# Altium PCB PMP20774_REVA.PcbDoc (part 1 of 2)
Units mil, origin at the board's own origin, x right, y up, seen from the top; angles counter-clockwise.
Board outline 2225 x 750 mil, 4 copper layers (Top Layer, Signal Layer 1, Signal Layer 2, Bottom Layer), stack 61.2 mil thick; 80 components, 51 nets, 281 pads, 110 vias.
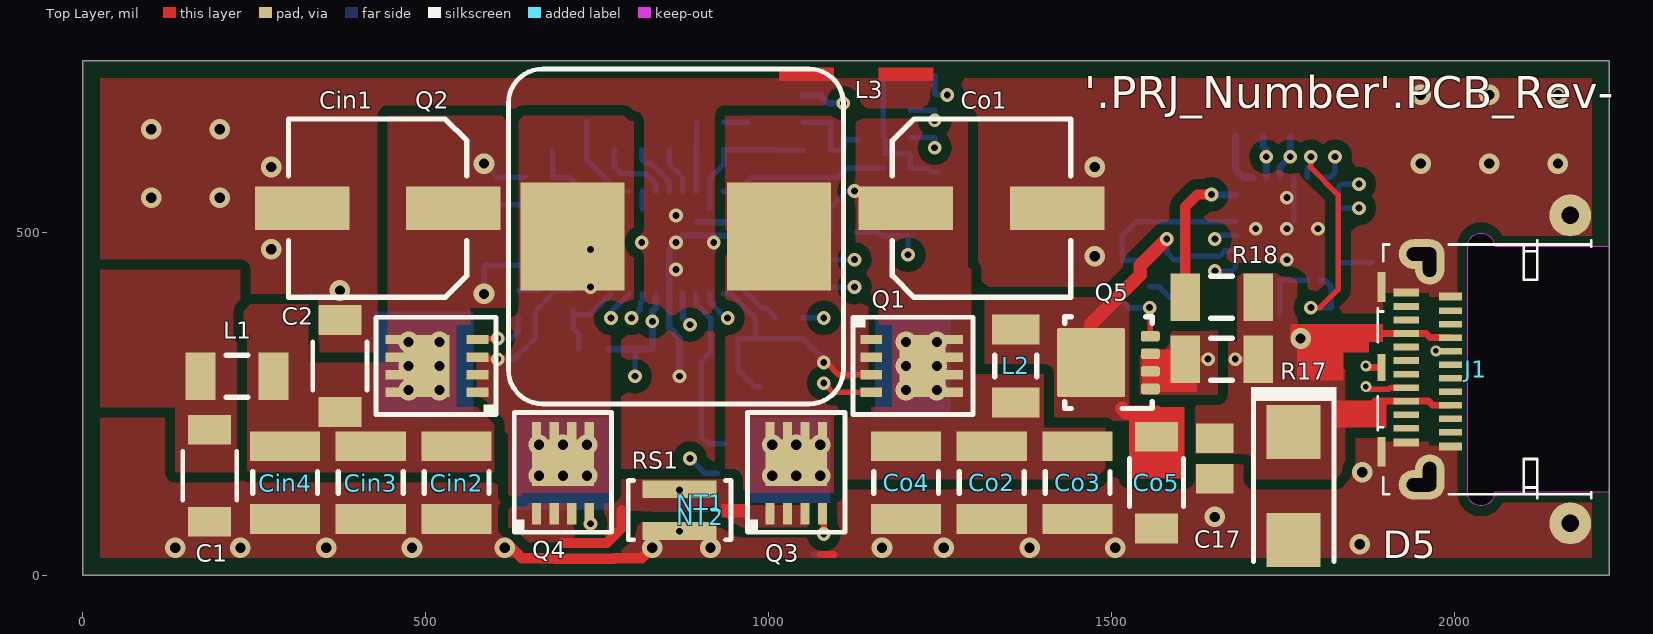
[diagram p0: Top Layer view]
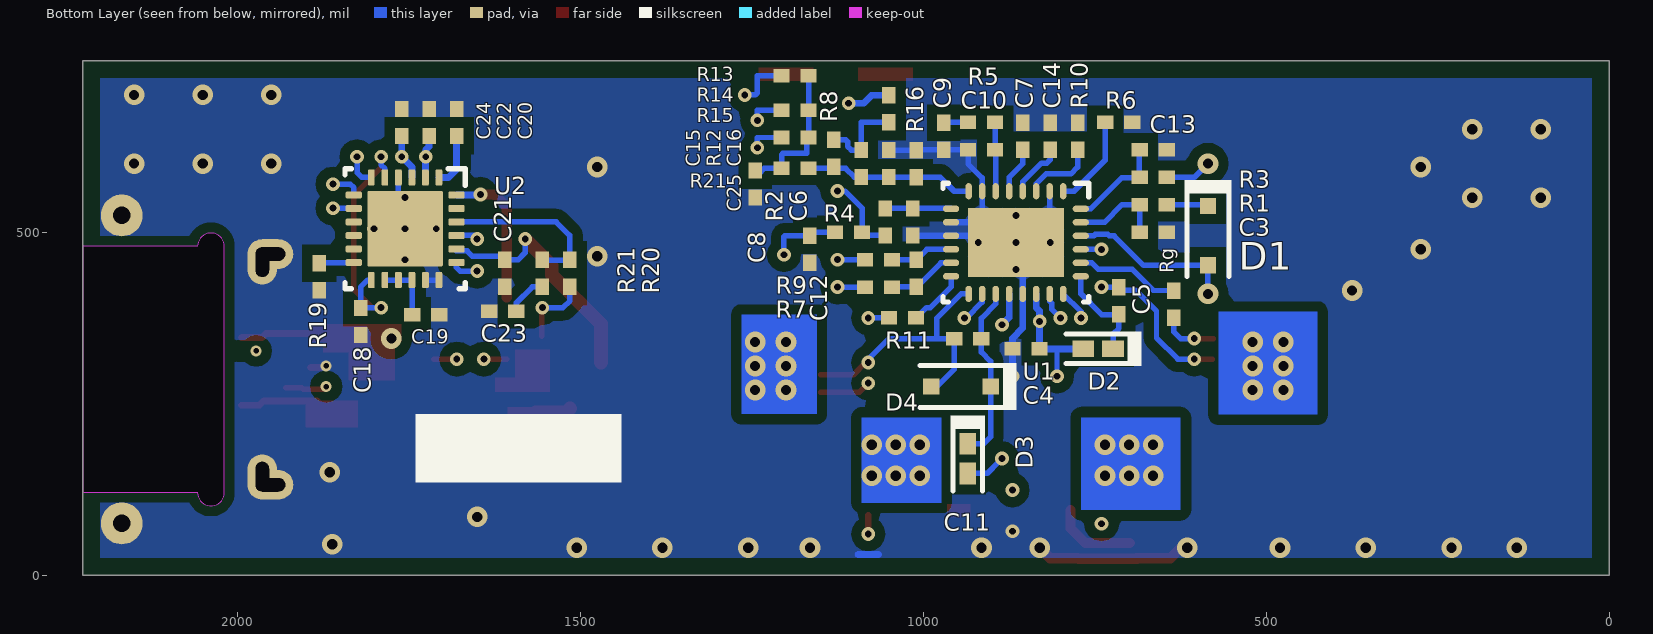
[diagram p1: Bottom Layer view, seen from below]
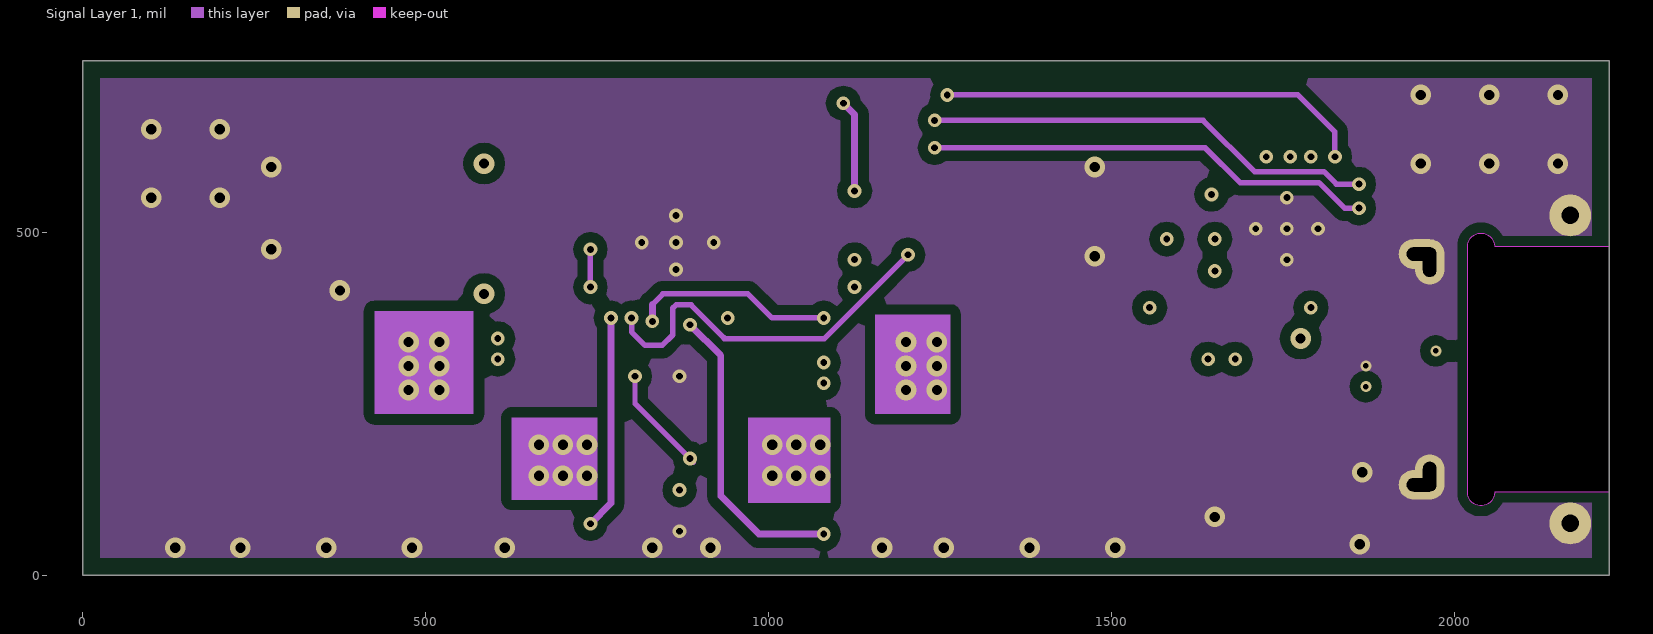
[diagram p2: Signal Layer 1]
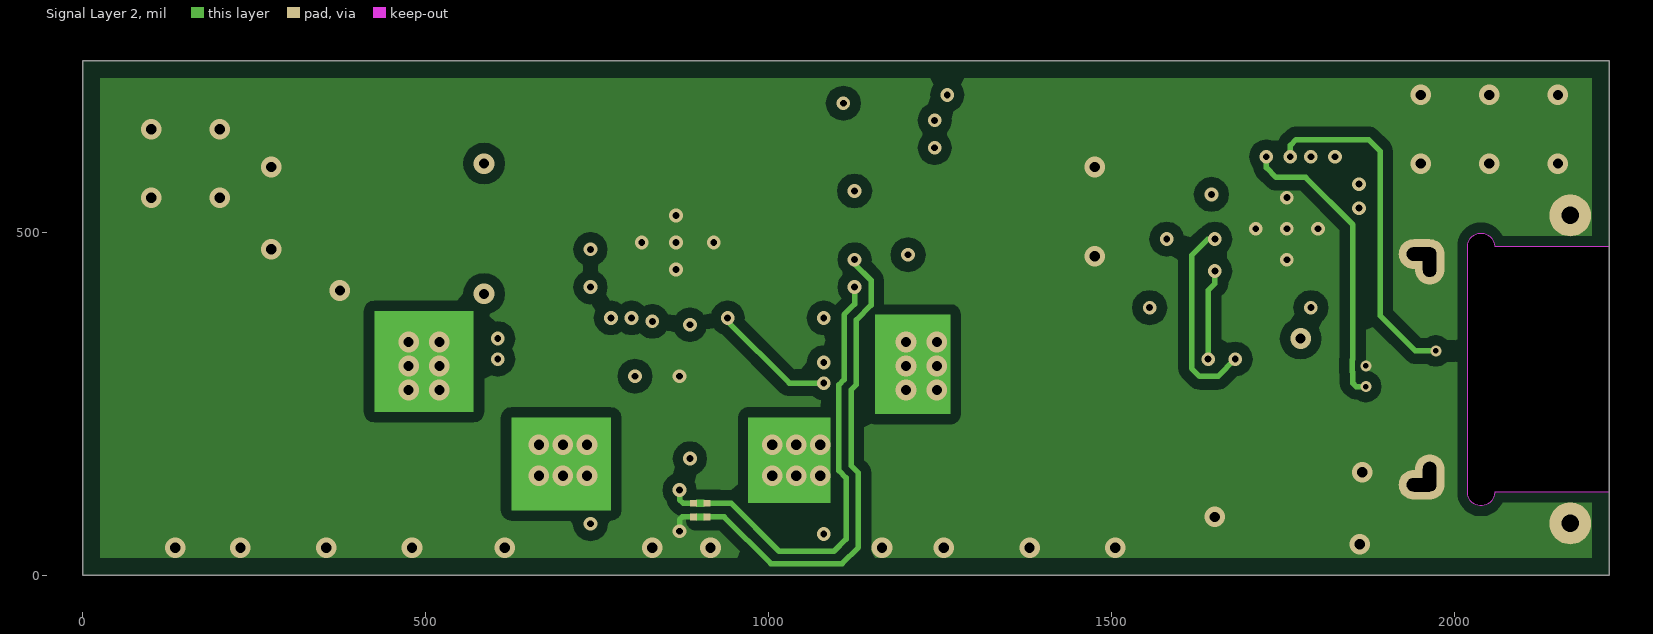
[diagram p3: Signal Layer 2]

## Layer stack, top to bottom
Top Solder: solder mask 0.4, Solder Resist, Dk 3.5
Top Layer: signal copper 1.4
Dielectric1: core 20, FR-4, Dk 4.8
Signal Layer 1: signal copper 0.7
Dielectric2: dielectric 17, FR-4, Dk 4.2
Signal Layer 2: signal copper 0.7
Dielectric 3: dielectric 20, FR-4, Dk 4.8
Bottom Layer: signal copper 1.4
Bottom Solder: solder mask 0.4, Solder Resist, Dk 3.5

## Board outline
0,0 2225,0 2225,750 0,750

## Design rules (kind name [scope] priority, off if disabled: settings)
AcuteAngle [All] p1: minimum=4.50000000000000E+0001 checktracksonly=FALSE
AssemblyTestPointUsage [All] p1: valid=2
BoardOutlineClearance BoardOutlineClearance_MountingHoles [OnCopper and InComponentClass('Mounting Holes')] p1: gap=40
BoardOutlineClearance BoardOutlineClearance_Poly [OnCopper and IsPoly] p2: gap=25
BoardOutlineClearance [OnCopper and Not InComponentClass('Logo') and not InComponentClass('FiducialMark') and not InRegion(1000,500,4000,800) and not InPoly] p3: gap=75
Clearance Clearance_Keepouts [((IsTrack Or IsArc) And Not InPoly) And IsFree and IsKeepOut vs ((IsTrack Or IsArc) And Not InPoly) And IsFree and IsKeepOut] p1: gap=0
Clearance Clearance_Poly [InPolygon] p2: gap=15
Clearance [All] p3: gap=7.87
ComponentClearance ComponentClearance_MountingHoles_FiducialMarks [InComponentClass('Mounting Holes') vs InComponentClass('FiducialMark')] p1: gap=50 collisioncheckmode=3 verticalgap=10 showdistances=FALSE
ComponentClearance ComponentClearance_Shunt [InComponentClass('Header') vs InComponentClass('Shunt')] p2: gap=0 collisioncheckmode=3 verticalgap=0 showdistances=FALSE
ComponentClearance ComponentClearance_Logo [InComponentClass('Logo')] p3: gap=50 collisioncheckmode=3 verticalgap=10 showdistances=FALSE
ComponentClearance ComponentClearance_ScrewToNut [(HasFootprint('NY PMS 440 0025 PH')) vs (HasFootprint('Keystone_1902C'))] p4: gap=5 collisioncheckmode=3 verticalgap=10 showdistances=FALSE
ComponentClearance ComponentClearance_MountingHoles [InComponentClass('Mounting Holes')] p5: gap=250 collisioncheckmode=3 verticalgap=100000 showdistances=FALSE
ComponentClearance ComponentClearance_SmallPassives [HasFootprint('0201*') or HasFootprint('0402*') or HasFootprint('0508') or HasFootprint('0603*') or HasFootprint('0612') or HasFootprint('0805*') or HasFootprint('0815*') or HasFootprint('0830*') or HasFootprint('1206*') or HasFootprint('1210*') or HasFootprint('1808*') or HasFootprint('1812*') or HasFootprint('1825*') or HasFootprint('2010*') or HasFootprint('2220*') or HasFootprint('2225*') or HasFootprint('2512*') or HasFootprint('2728*') or HasFootprint('3518*') vs HasFootprint('0201*') or HasFootprint('0402*') or HasFootprint('0508') or HasFootprint('0603*') or HasFootprint('0612') or HasFootprint('0805*') or HasFootprint('0815*') or HasFootprint('0830*') or HasFootprint('1206*') or HasFootprint('1210*') or HasFootprint('1808*') or HasFootprint('1812*') or HasFootprint('1825*') or HasFootprint('2010*') or HasFootprint('2220*') or HasFootprint('2225*') or HasFootprint('2512*') or HasFootprint('2728*') or HasFootprint('3518*')] p6: gap=14.96 collisioncheckmode=3 verticalgap=10 showdistances=FALSE
ComponentClearance ComponentClearance_THtoSMT [IsThruComponent vs IsSMTComponent] p7: gap=40 collisioncheckmode=3 verticalgap=30 showdistances=FALSE
ComponentClearance ComponentClearance_THtoTH [IsThruComponent vs IsThruComponent] p8: gap=30 collisioncheckmode=3 verticalgap=30 showdistances=FALSE
ComponentClearance [All] p9: gap=9 collisioncheckmode=3 verticalgap=10 showdistances=FALSE
DiffPairsRouting [All] p1: maxlimit=100 minlimit=10 mostfreqgap=10 toplayer_minwidth=8 toplayer_maxwidth=15 toplayer_prefwidth=8 midlayer1_minwidth=8 midlayer1_maxwidth=15 midlayer1_prefwidth=8 midlayer2_minwidth=8 midlayer2_maxwidth=15 midlayer2_prefwidth=8 bottomlayer_minwidth=8 bottomlayer_maxwidth=15 bottomlayer_prefwidth=8 maxuncoupledlength=1000
FabricationTestPointUsage TestPointUsage [All] p1: valid=2 allowmultiple=FALSE
FabricationTestpoint Testpoint [All] p1: side=3 testpointundercomponent=TRUE minsize=40 maxsize=100 preferedsize=60 minholesize=0 maxholesize=40 preferedholesize=32 testpointgrid=1 allowsidetop=TRUE allowsidebottom=TRUE usegrid=TRUE gridtolerance=0.01
FanoutControl Fanout_LCC [IsLCC] p1: bgadir=Out bgaviamode=Centered fanoutstyle=Auto fanoutdirection=Alternating viagrid=1 // Fanout_LCC (Default Rule)
FanoutControl Fanout_BGA [IsBGA] p2: bgadir=Out bgaviamode=Centered fanoutstyle=Auto fanoutdirection=Alternating viagrid=1 // Fanout_BGA (Default Rule)
FanoutControl Fanout_Default [All] p4: bgadir=Out bgaviamode=Centered fanoutstyle=Auto fanoutdirection=Alternating viagrid=1 // Fanout_Default (Default Rule)
FanoutControl Fanout_Small [(CompPinCount < 5)] p5: bgadir=Out bgaviamode=Centered fanoutstyle=Auto fanoutdirection=OutThenIn viagrid=1 // Fanout_Small (Default Rule)
HoleSize [All] p1: absolutevalues=TRUE maxlimit=251 minlimit=7.87 maxpercent=80.000 minpercent=20.000
MinimumAnnularRing MinimumAnnularRing_ThermalPadVias [IsVia and InAnyComponent] p1: minimumring=4.99
MinimumAnnularRing [All] p2: minimumring=4.99
MinimumSolderMaskSliver MinimumSolderMaskSliver_Logo [InComponentClass('Logo') vs InComponentClass('Logo')] p1: minsoldermaskwidth=0.7
MinimumSolderMaskSliver [All] p2: minsoldermaskwidth=3.94
PlaneConnect [All] p1: planeconnectstyle=Direct reliefexpansion=10 reliefentries=4 reliefconductorwidth=10 reliefairgap=10
PolygonConnect [All] p1: connectstyle=Direct reliefconductorwidth=10 reliefentries=4 polygonreliefangle="90 Angle" airgapwidth=10
RoutingVias ThermalPadVias [IsVia and InAnyComponent] p1: holewidth=7.87 width=19.68 viastyle="Through Hole" minholewidth=7.87 minwidth=19.68 maxholewidth=12.99 maxwidth=23.62
RoutingVias [All] p2: holewidth=16 width=34 viastyle="Through Hole" minholewidth=7.87 minwidth=26 maxholewidth=40 maxwidth=65
SilkToBoardRegionClearance [Not ((IsComment or IsDesignator) And (Hide <> 'False')) and not InRegion(1000,500,4000,800)] p1:
SilkToSilkClearance SilkToSilkClearance_Pb-FreeLogo [(HasFootprint('Pb-Free_Overlay_Medium') OR HasFootprint('Pb-Free_Overlay_Small')) vs (HasFootprint('Pb-Free_Overlay_Medium') OR HasFootprint('Pb-Free_Overlay_Small'))] p1: silktosilkclearance=0
SilkToSilkClearance [All] p2: silktosilkclearance=4
SilkToSolderMaskClearance SilkToComponentPadClearance [(IsPad or IsFill or IsRegion) and InAnycomponent] p1: minsilkscreentomaskgap=5 clearancetoexposedcopper=TRUE
SilkToSolderMaskClearance "Silk to Solder Mask Opening" [All] p2: minsilkscreentomaskgap=4 clearancetoexposedcopper=FALSE
SolderMaskExpansion [All] p1: expansion=1.97
Width [All] p1: maxlimit=100 minlimit=6 preferedwidth=10 checkconnectedcopper=TRUE
15 further rules are at their usual default settings.

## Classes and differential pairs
component class AssemblyNote: ZZ1 ZZ2 ZZ3 ZZ4
component class PMP20774_REVA_Hardware: ZZ1 ZZ2 ZZ3 ZZ4
component class PMP20774_DCDC_REVA: C1 C2 C3 C4 C5 C6 C7 C8 C9 C10 C11 C12 C13 C14 C15 C16 C25 Cin1 Cin2 Cin3 Cin4 Co1 Co2 Co3 Co4 Co5 D1 D2 D3 D4 L1 L2 L3 NT1 NT2 Q1 Q2 Q3 Q4 R1 R2 R3 R4 R5 R6 R7 R8 R9 R10 R11 R12 R13 R14 R15 R16 R21 Rg RS1 U1
component class PMP20774_PD_REVA: C17 C18 C19 C20 C21 C22 C23 C24 D5 J1 Q5 R17 R18 R19 R20 R21 U2
differential pair CS: +CS_P -CS_N
differential pair HDRV1: +HDRV1_P -HDRV1_N
differential pair HDRV2: +HDRV2_P -HDRV2_N

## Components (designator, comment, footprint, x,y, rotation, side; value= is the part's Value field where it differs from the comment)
C1 "GRM31CR71H475KA12L" 1206_180 185,145 r270 top
C2 "GRM31CR71H475KA12L" 1206_180 375,305 r90 top
C3 "GCM155R71H104KE02D" 0402L#1 664.84,500 r180 bottom
C4 "C1005X5R1C105K050BC" 0402L#1 850,330 r0 bottom
C5 "GCM155R71H104KE02D" 0402L#1 715,400 r90 bottom
C6 "CC0402KRX7R9BB101" 0402L#1 1015,515 r270 bottom
C7 "GRM155R71H104ME14D" 0402L#1 854.84,639.84 r90 bottom
C8 "C1005X5R1E224M050BC" 0402L#1 1165,475 r270 bottom
C9 "GCM155R71H223KA55D" 0402L#1 969.84,639.84 r270 bottom
C10 "GRM155R71H102KA01D" 0402L#1 914.84,619.84 r0 bottom
C11 "GCM155R71H104KE02D" 0402L#1 935,345 r180 bottom
C12 "CC0402KRX7R9BB101" 0402L#1 1010,440 r90 bottom
C13 "CC0402KRX7R9BB101" 0402L#1 664.84,620 r0 bottom
C14 "CC0402KRX7R9BB101" 0402L#1 814.84,639.84 r90 bottom
C15 "GCM155R71H223KA55D" 0402L#2 1130,620 r270 bottom
C16 "GRM155R71H104ME14D" 0402L#1 1050,600 r90 bottom
C17 "GRM21BR71E475KA73L" 0805L 1650,170 r270 top
C18 "GRM155R71A224KE01D" 0402L#1 1820,370 r90 bottom
C19 "GRM155R71H104ME14D" 0402L#1 1725,380 r180 bottom
C20 "GRM155R71H104ME14D" 0402L#1 1680,660 r90 bottom
C21 "GRM155R71H104ME14D" 0402L#1 1610,440 r270 bottom
C22 "GRM1555C1H561JA01D" 0402L#1 1720,660 r90 bottom
C23 "GCM155R71E103KA37D" 0402L#1 1612.76,385 r0 bottom
C24 "GRM1555C1H561JA01D" 0402L#1 1760,660 r90 bottom
C25 "DNP" 0402L#1 1245,570 r270 bottom
Cin1 "865080645012" WCAP-ASLI_630x770 430,535 r180 top
Cin2 "GRM32ER71H106KA12L" 1210_270L 545,135 r270 top
Cin3 "GRM32ER71H106KA12L" 1210_270L 420,135 r270 top
Cin4 "GRM32ER71H106KA12L" 1210_270L 295,135 r270 top
Co1 "865080445010" WCAP-ASLI_630x770 1310,535 r0 top
Co2 "GRM32ER71H106KA12L" 1210_270L 1325,135 r270 top
Co3 "GRM32ER71H106KA12L" 1210_270L 1450,135 r270 top
Co4 "GRM32ER71H106KA12L" 1210_270L 1200,135 r270 top
Co5 "GRM31CR71H475KA12L" 1206_180 1565,135 r270 top
D1 "BAT54HT1G" SOD-323 585,495 r270 bottom
D2 "BAS516,115" SOD-523 745,330 r0 bottom
D3 "BAS516,115" SOD-523 935,170 r270 bottom
D4 "MMSZ5237BS-7-F" sod-323 945,275 r0 bottom
D5 "B340A-13-F" SMA 1765,130 r270 top
J1 "20-0000016-01" Lintes_20-0000016-01 2225,300 r90 top
L1 "BLM31SN500SN1L" 1206L 225,290 r0 top
L2 "FBMJ3216HM600-T" 1206L 1360,305 r90 top
L3 "744325550" WE-HC6 864.57,493.78 r0 top
NT1 "Net-Tie" Net-Tie_10mil 900,105 r0 top net-tie
NT2 "Net-Tie" Net-Tie_10mil 900,85 r0 top net-tie
Q1 "BSZ042N06NS" PG-TSDSON-8#1 1210,305 r0 top
Q2 "BSZ042N06NS" PG-TSDSON-8#1 515,305 r180 top
Q3 "BSZ042N06NS" PG-TSDSON-8#1 1040,150 r90 top
Q4 "BSZ042N06NS" PG-TSDSON-8#2 685,150 r90 top
Q5 "CSD17579Q3A" DNH0008A_NV 1495,310 r180 top
R1 "CRCW040210R0JNED" 0402L#1 664.84,540 r180 bottom
R2 "CRCW040210R0JNED" 0402L#1 1055,515 r270 bottom
R3 "CRCW040210R0JNED" 0402L#1 664.84,580 r0 bottom
R4 "CRCW040210R0JNED" 0402L#1 1108.66,500 r180 bottom
R5 "CRCW04022K49FKED" 0402L#1 914.84,659.84 r180 bottom
R6 "CRCW040293K1FKED" 0402L#1 715,660 r180 bottom
R7 "CRCW0402100RFKED" 0402L#1 1065,420 r0 bottom
R8 "CRCW040247R0JNED" 0402L#1 1049.84,679.84 r270 bottom
R9 "CRCW0402100RFKED" 0402L#1 1065,460 r0 bottom
R10 "CRCW040271K5FKED" 0402L#1 774.84,639.84 r270 bottom
R11 "CRCW040220K0JNED" 0402L#1 1030,375 r0 bottom
R12 "CRCW040249K9FKED" 0402L#1 1090,600 r90 bottom
R13 "CRCW04026K65FKED" 0402L#1 1186.72,727.97 r180 bottom
R14 "CRCW04029K76FKED" 0402L#1 1186.72,677.97 r180 bottom
R15 "CRCW04028K06FKED" 0402L#1 1186.72,637.97 r180 bottom
R16 "CRCW04029K53FKED" 0402L#1 1009.84,599.84 r270 bottom
R17 "WSL12065L000FEA" 1206L 1660,315 r0 top
R18 "ERJ-P08J121V" 1206L 1660,405 r0 top
R19 "CRCW0402100KJNED" 0402L#1 1880,435 r270 bottom
R20 "CRCW040210R0FKED" 0402L#1 1515,440 r270 bottom
R21 "CRCW04021K00FKED" 0402L#1 1555,440 r90 bottom
R21 "CRCW04020000Z0ED" 0402L#1 1186.72,592.97 r0 bottom
Rg "CRCW04023R00JNED" 0402L#1 635,395 r270 bottom
RS1 "PRL1632-R010-F-T1" 0612 870,95 r90 top
U1 "LM5175RHFR" RHF0028A 864.84,484.84 r270 bottom
U2 "TPS25740BRGER" RGE0024F 1755,505 r270 bottom
ZZ1 "This Assembly Note is for PCB labels only" AssemblyNoteLabel 185,3938 r0 top
ZZ2 "These assemblies are ESD sensitive, ESD precautions shall be observed." AssemblyNote 185,3829.11 r0 top
ZZ3 "These assemblies must be clean and free from flux and all contaminants. Use of no clean flux is not acceptable." AssemblyNote 185,3740.56 r0 top
ZZ4 "These assemblies must comply with workmanship standards IPC-A-610 Class 2, unless otherwise specified." AssemblyNote 185,3652 r0 top

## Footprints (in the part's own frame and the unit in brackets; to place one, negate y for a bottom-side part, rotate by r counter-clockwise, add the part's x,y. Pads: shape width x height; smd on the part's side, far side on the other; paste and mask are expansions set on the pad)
0402L#1 [mm] "0402 from SM-752 data"
  rect 0.6x0.5 smd: 1(-0.5,0) 2(0.5,0)
  body extent -0.55,-0.3 0.55,0.3, height 0.6
0402L#2 [mm] "0402 from SM-752 data"
  rect 0.6x0.5 smd: 1(-0.373,0) 2(0.627,0)
  body extent -0.42,-0.3 0.68,0.3, height 0.6
0612 [mm] "Panasonic recommended land pattern, fb97d03ed01.pdf dated April 2008"
  rect 0.65x2.75 smd: 1(-0.775,0) 2(0.775,0)
  silkscreen extent -1.1,-1.9 1.1,1.9, body extent -0.9,-1.7 0.9,1.7, height 0.85
0805L [mm] "0805 from SM-752 data"
  rect 1.1x1.4 smd: 1(-0.75,0) 2(0.75,0)
  body extent -1.1,-0.72 1.1,0.72, height 1.45
1206_180 [mm] "1206_180"
  rect 1.1x1.6 smd: 1(-1.7,0) 2(1.7,0)
  silkscreen extent -0.9,-1 0.9,1, body extent -1.75,-0.95 1.75,0.95, height 1.8
1206L [mm] "1206 from SM-752 data"
  rect 1.1x1.75 smd: 1(-1.35,0) 2(1.35,0)
  silkscreen extent -0.4,-0.77 0.4,0.77, body extent -1.7,-0.9 1.7,0.9, height 1.35
1210_270L [mm] "1210"
  rect 1.1x2.6 smd: 1(-1.35,0) 2(1.35,0)
  silkscreen extent -0.4,-1.2 0.4,1.2, body extent -1.7,-1.35 1.7,1.35, height 2.7
AssemblyNote [mil] "Assembly Note"
AssemblyNoteLabel [mil] "Assembly Note for PCB Labels"
DNH0008A_NV [mm] "8 pin VSONP, 0.65 mm pitch"
  rrect50% 0.7x0.4 smd paste-0.05 mask-0.05: 1(-1.55,0.975) 2(-1.55,0.325) 3(-1.55,-0.325) 4(-1.55,-0.975) 5(1.55,-0.975) 6(1.55,-0.325) 7(1.55,0.325) 8(1.55,0.975)
  rrect14% 0.705x1.125 on Top Paste: 9(-0.208,0.662) 9(-0.208,-0.663) 9(0.697,0.662) 9(0.697,-0.663)
  rrect6% 1.775x2.45 on Top Solder: 9(0.327,0)
  rrect4% 2.51x2.55 smd paste-1.5 mask-1.5: 9(0.645,0)
  rect 0.5x0.3 on Top Solder: 9(1.175,0.975) 9(1.175,-0.325) 9(1.175,0.325) 9(1.175,-0.975)
  silkscreen extent -1.62,-1.7 1.62,1.7, body extent -1.65,-1.65 1.65,1.66, height 0.91
Lintes_20-0000016-01 [mm] "Connector, Receptacle, USB Type C, SMT"
  rect 1.1x0.3 smd: 1(3.05,8.44) 3(-3.05,8.44)
  rect 1x0.3 smd: 2(0.07,8.44)
  rect 0.3x0.95 smd: A1(-2.7,7.525) A12(2.85,7.525)
  rect 0.25x0.95 smd: A2(-2.175,7.525) A3(-1.675,7.525) A4(-1.175,7.525) A5(-0.675,7.525) A6(-0.175,7.525) A7(0.325,7.525) A8(0.825,7.525) A9(1.325,7.525) A10(1.825,7.525) A11(2.325,7.525)
  rect 0.3x0.85 smd: B1(2.7,5.875) B12(-2.85,5.875)
  rect 0.25x0.85 smd: B2(2.175,5.875) B3(1.675,5.875) B4(1.175,5.875) B5(0.675,5.875) B6(0.175,5.875) B7(-0.325,5.875) B8(-0.825,5.875) B9(-1.325,5.875) B10(-1.825,5.875) B11(-2.325,5.875)
  oval 1.1x1.7 hole 0.5 slot 1.1 at 90 deg: H1(4.27,6.95) H3(-4.27,6.95)
  oval 1.65x1.1 hole 0.5 slot 1.095 at 0 deg: H2(3.97,6.65) H4(-3.97,6.65)
  round 1.55 hole 0.65: H5(5.7,1.45) H6(-5.7,1.45)
  Keep-Out Layer board cut-out: -4.55,0 -4.55,4.25 -4.767,4.3 -4.941,4.438 -5.037,4.639 -5.037,4.861 -4.941,5.062 -4.767,5.2 -4.55,5.25 -4.55,5.25 -4.55,5.25 4.55,5.25 4.55,5.25 4.767,5.2 4.941,5.062 5.037,4.861 5.037,4.639 4.941,4.438 4.767,4.3 4.55,4.25 4.55,4.25 4.55,0
  silkscreen extent -4.77,0.68 4.77,8.58, body extent -5.8,-1.56 5.8,8.59, height 2.44
Net-Tie_10mil [mil] "10mil net tie, no solder mask opening, no solder paste"
  rect 10x10 on Mid2 paste-5 mask-5: 1(-10,0) 2(10,0)
  Signal Layer 2 region: -6,5 6,5 6,-5 -6,-5
PG-TSDSON-8#1 [mm] "Infineon recommended land pattern"
  rect 0.8x0.34 smd: 1(-1.538,0.975) 2(-1.538,0.325) 3(-1.538,-0.325) 4(-1.538,-0.975)
  rect 0.65x0.34 smd: 5(1.538,-0.975) 6(1.538,-0.325) 7(1.538,0.325) 8(1.538,0.975)
  rect 1.71x2.29 smd: 9(0.358,0)
  silkscreen extent -2.22,-1.8 2.22,1.8, body extent -1.7,-1.7 1.7,1.7, height 1.1
PG-TSDSON-8#2 [mm] "Infineon recommended land pattern"
  rect 0.8x0.34 smd: 1(-1.538,0.594) 2(-1.538,-0.056) 3(-1.538,-0.706) 4(-1.538,-1.356)
  rect 0.65x0.34 smd: 5(1.538,-1.356) 6(1.538,-0.706) 7(1.538,-0.056) 8(1.538,0.594)
  rect 1.71x2.29 smd: 9(0.358,-0.381)
  silkscreen extent -2.22,-2.18 2.22,1.42, body extent -1.7,-2.08 1.7,1.32, height 1.1
RGE0024F [mm] "QFN, 24-Leads, Body 4x4mm, Pitch 0.5mm, Thermal Pad 2.8x2.8mm, TI Recommended"
  rrect40% 0.6x0.25 smd: 1(-1.9,1.25) 2(-1.9,0.75) 3(-1.9,0.25) 4(-1.9,-0.25) 5(-1.9,-0.75) 6(-1.9,-1.25) 13(1.9,-1.25) 14(1.9,-0.75) 15(1.9,-0.25) 16(1.9,0.25) 17(1.9,0.75) 18(1.9,1.25)
  rrect40% 0.25x0.6 smd: 7(-1.25,-1.9) 8(-0.75,-1.9) 9(-0.25,-1.9) 10(0.25,-1.9) 11(0.75,-1.9) 12(1.25,-1.9) 19(1.25,1.9) 20(0.75,1.9) 21(0.25,1.9) 22(-0.25,1.9) 23(-0.75,1.9) 24(-1.25,1.9)
  rrect8% 1.23x1.23 on Bottom Paste: 25(-0.715,-0.715) 25(-0.715,0.715) 25(0.715,-0.715) 25(0.715,0.715)
  rrect4% 2.8x2.8 smd paste-1.4: 25(0,0)
  silkscreen extent -2.22,-2.22 2.22,2.22, body extent -2.07,-2.07 2.08,2.08, height 1.01
RHF0028A [mm] "QFN, 28-Leads, Body 5x4mm, Pitch 0.5mm, Thermal Pad 3.55x2.55mm"
  oval 0.6x0.24 smd: 1(-1.9,1.75) 2(-1.9,1.25) 3(-1.9,0.75) 4(-1.9,0.25) 5(-1.9,-0.25) 6(-1.9,-0.75) 7(-1.9,-1.25) 8(-1.9,-1.75) 15(1.9,-1.75) 16(1.9,-1.25) 17(1.9,-0.75) 18(1.9,-0.25) 19(1.9,0.25) 20(1.9,0.75) 21(1.9,1.25) 22(1.9,1.75)
  oval 0.24x0.6 smd: 9(-1.25,-2.4) 10(-0.75,-2.4) 11(-0.25,-2.4) 12(0.25,-2.4) 13(0.75,-2.4) 14(1.25,-2.4) 23(1.25,2.4) 24(0.75,2.4) 25(0.25,2.4) 26(-0.25,2.4) 27(-0.75,2.4) 28(-1.25,2.4)
  rect 2.55x3.55 smd paste-3.55: 29(0,0)
  silkscreen extent -2.2,-2.7 2.2,2.7, body extent -2.07,-2.57 2.07,2.57, height 1.01
SMA [mm] "Molded Diode, 2-Leads, Body 4.3x2.6mm, IPC Medium Density, based on OnSemi component dimensions and land pattern"
  rect 2x2 smd: 1(-2,0) 2(2,0)
  silkscreen extent -3.66,-1.57 2.79,1.57, body extent -2.6,-1.3 2.6,1.3, height 2.42
SOD-323 [mm] "NXP recommended land pattern"
  rect 0.6x0.6 smd paste-0.05: 1(-1.1,0) 2(1.1,0)
  silkscreen extent -2.06,-0.86 1.53,0.86, body extent -1.3,-0.67 1.3,0.68, height 1.1
sod-323 [mm] "NXP recommended land pattern"
  rect 0.6x0.6 smd paste-0.05: 1(-1.1,0) 2(1.1,0)
  silkscreen extent -2.06,-0.86 1.53,0.86, body extent -1.3,-0.67 1.3,0.68, height 1.1
SOD-523 [mm] "NXP Semiconductor recommended land pattern, nominal STEP model"
  rect 0.8x0.6 smd paste-0.05: 1(-0.55,0) 2(0.55,0)
  silkscreen extent -1.6,-0.64 1.2,0.64, body extent -0.8,-0.4 0.8,0.4, height 0.72
WCAP-ASLI_630x770 [mm] "SMD, 2-Leads, Dia 6.3mm"
  rect 3.5x1.6 smd: 1(-2.8,0) 2(2.8,0)
  silkscreen extent -3.3,-3.3 3.3,3.3, body extent -3.3,-3.3 3.3,3.3, height 7.7
WE-HC6 [mm] "Wurth Electronik recommended land pattern"
  rect 3.85x4 smd: 1(-3.825,0) 2(3.825,0)
  silkscreen extent -6.2,-6.2 6.2,6.2, body extent -5.76,-5.36 5.74,5.34, height 5

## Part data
C1 C2 Co5: "CAP, CERM, 4.7 µF, 50 V, +/- 10%, X7R, 1206"
C3 C5 C11: "CAP, CERM, 0.1 µF, 50 V, +/- 10%, X7R, AEC-Q200 Grade 1, 0402"
C4: "CAP, CERM, 1 µF, 16 V, +/- 10%, X5R, 0402"
C6 C12 C13 C14: "CAP, CERM, 100 pF, 50 V, +/- 10%, X7R, 0402"
C7 C16 C19 C20 C21: "CAP, CERM, 0.1 µF, 50 V, +/- 20%, X7R, 0402"
C8: "CAP, CERM, 0.22 µF, 25 V, +/- 20%, X5R, 0402"
C9 C15: "CAP, CERM, 0.022 µF, 50 V, +/- 10%, C0G/NP0, 0402"
C10: "CAP, CERM, 1000 pF, 50 V, +/- 10%, X7R, 0402"
C17: "CAP, CERM, 4.7 µF, 25 V, +/- 10%, X7R, 0805"
C18: "CAP, CERM, 0.22 µF, 10 V, +/- 10%, X7R, 0402"
C22 C24: "CAP, CERM, 560 pF, 50 V, +/- 5%, C0G/NP0, 0402"
C23: "CAP, CERM, 0.01 µF, 25 V, +/- 10%, X7R, 0402"
C25: library part GRM155R70J105MA12D, "CAP, CERM, 1 µF, 6.3 V, +/- 20%, X7R, 0402"
Cin1: "CAP, AL, 47 µF, 50 V, +/- 20%, SMD"
Cin2 Cin3 Cin4 Co2 Co3 Co4: "CAP, CERM, 10 µF, 50 V, +/- 10%, X7R, 1210"
Co1: "CAP, AL, 100 µF, 25 V, +/- 20%, SMD"
D1: "Diode, Schottky, 30 V, 0.2 A, SOD-323"
D2 D3: "Diode, Switching, 100V, 0.25A, SOD-523"
D4: "Diode, Zener, 8.2 V, 200 mW, SOD-323"
D5: "Diode, Schottky, 40 V, 3 A, SMA"
J1: "Connector, Receptacle, USB Type C, R/A, SMT"
L1: "Ferrite Bead, 50 ohm @ 100 MHz, 12 A, 1206"
L2: "Ferrite Bead, 60 ohm @ 100 MHz, 4 A, 1206"
L3: "Inductor, Shielded Drum Core, Superflux, 5.5 µH, 10 A, 0.0112 ohm, SMD"
NT1 NT2: "Single point connection between nets."
Q1 Q2 Q3 Q4: "MOSFET, N-CH, 60 V, 17 A, PG-TSDSON-8"
Q5: "MOSFET, N-CH, 30 V, 20 A, DNH0008A (VSONP-8)"
R1 R2 R3 R4: "RES, 10, 5%, 0.063 W, 0402"
R5: "RES, 2.49 k, 1%, 0.063 W, 0402"
R6: "RES, 93.1 k, 1%, 0.063 W, 0402"
R7 R9: "RES, 100, 1%, 0.063 W, 0402"
R8: "RES, 47, 5%, 0.063 W, 0402"
R10: "RES, 71.5 k, 1%, 0.063 W, 0402"
R11: "RES, 20 k, 5%, 0.063 W, 0402"
R12: "RES, 49.9 k, 1%, 0.063 W, 0402"
R13: "RES, 6.65 k, 1%, 0.063 W, 0402"
R14: "RES, 9.76 k, 1%, 0.063 W, 0402"
R15: "RES, 8.06 k, 1%, 0.063 W, 0402"
R16: "RES, 9.53 k, 1%, 0.063 W, 0402"
R17: "RES, 0.005, 1%, 0.25 W, 1206"
R18: "RES, 120, 5%, 0.667 W, AEC-Q200 Grade 0, 1206"
R19: "RES, 100 k, 5%, 0.063 W, 0402"
R20: "RES, 10.0, 1%, 0.063 W, 0402"
R21: "RES, 1.00 k, 1%, 0.063 W, 0402"
R21: "RES, 0, 5%, 0.063 W, 0402"
Rg: "RES, 3.0, 5%, 0.063 W, 0402"
RS1: "RES, 0.01, 1%, 1 W, 0612"
U1: "42-V Wide VIN Synchronous 4-Switch Buck-Boost Controller, RHF0028A"
U2: "USB Type-C and USB PD Source Controller, RGE0024F (VQFN-24)"
ZZ1: library part AssemblyNoteLabel
ZZ2 ZZ3 ZZ4: library part AssemblyNote

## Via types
v1: diameter 30, hole 15, Top Layer to Bottom Layer, 56 vias
v2: diameter 20, hole 10, Top Layer to Bottom Layer, 51 vias
v3: diameter 16, hole 8, Top Layer to Bottom Layer, 2 vias
v4: diameter 16, hole 8, Top Layer to Bottom Layer, tented both sides, 1 vias

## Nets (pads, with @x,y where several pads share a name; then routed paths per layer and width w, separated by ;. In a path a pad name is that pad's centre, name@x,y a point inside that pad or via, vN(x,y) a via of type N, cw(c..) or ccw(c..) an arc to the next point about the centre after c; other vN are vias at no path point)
BIAS: C8.1 R4.1 U1.21 | length 695.5
  Signal Layer 1 w8: v2(800,375) 800,354.57 819.57,335 844.69,335 860,350.31 860,389.28 864.84,394.13 886.81,394.13 935,345.93 935,345 1080.98,345 v2(1202.99,467.01)
  Bottom Layer w8: v2(800,375) 812.54,387.54 812.54,396.28 815.63,399.37 U1.21@815.63,410.04 ; R4.1@1128.35,500 1159.68,500 C8.1@1165,494.68 1201.54,494.68 1202.99,493.24 v2(1202.99,467.01)
BOOT1: C5.1 D2.1 U1.23 | length 152.1
  Bottom Layer w8: C5.1@714.84,385.16 714.84,359.76 723.35,351.26 D2.1@723.35,330 ; C5.1@715,380.32 715.39,379.92 740,379.92 770.35,410.28 U1.23@770.35,435.63
BOOT2: C11.2 D3.1 D4.1 U1.17 | length 260.1
  Bottom Layer w8: U1.17@894.37,410.04 894.37,395.31 915.31,374.37 C11.2@915.31,345 915.31,325.31 901.69,311.69 D4.1@901.69,275 901.69,201.81 911.85,191.65 D3.1@935,191.65
CC1: C22.1 J1.A5 U2.2 | length 552.5
  Top Layer w8: v3(1870,275) 1873.77,271.23 1903.53,271.23 1905.72,273.42 J1.A5@1928.74,273.42
  Signal Layer 2 w8: v2(1725,610) 1725,594 1739.2,579.8 1782.2,579.8 1851,511 1851,314.98 1850.13,314.11 1850.13,296.77 1851,295.89 1851,280 1856,275 v3(1870,275)
  Bottom Layer w10: C22.1@1720,640.32 1720,624.57 1725,619.57 v2(1725,610) ; U2.2@1725.47,579.8 v2@1725.47,609.53
CC2: C24.1 J1.B5 U2.3 | length 566.6
  Signal Layer 2 w8: v2(1760,610) 1760,626.54 1768.46,635 1874,635 1891,618 1891,378.4 1942.4,327 v4(1972,327)
  Bottom Layer w10: U2.3@1745.16,579.8 1745.16,595.16 v2(1760,610) C24.1@1760,640.32
COMP: C10.1 R5.2 U1.6 | length 99.4
  Bottom Layer w8: U1.6@894.37,559.65 C10.1@894.37,619.06 ; C10.1@895.16,619.84 R5.2@895.16,659.84
CS_N: NT2.2 R9.2 | length 748.6
  Signal Layer 2 w8: NT2.2@906,85 935,85 1003,17 1107,17 1130.62,40.62 1130.62,149.27 1120,159.89 1120,270 1127.73,277.73 1127.73,372.27 1149,393.54 1149,429.94 1125,453.94 v2(1125,460)
  Bottom Layer w8: R9.2@1084.69,460 v2(1125,460)
CS_P: NT1.2 R7.2 | length 660.5
  Signal Layer 2 w8: NT1.2@910,105 945,105 1015,35 1095,35 1112.62,52.62 1112.62,141.82 1102,152.44 1102,277.46 1109.73,285.18 1109.73,379.73 1125,395 v2(1125,420)
  Bottom Layer w8: R7.2@1084.69,420 v2(1125,420)
CTL1: R13.1 U2.6 | length 750.1
  Signal Layer 1 w8: v2(1260,700) 1771,700 1825,646 v2(1825,610)
  Bottom Layer w8: R13.1@1206.4,727.97 1241.72,727.97 1241.72,702.97 1244.69,700 v2(1260,700) ; U2.6@1804.21,579.8 1818.11,579.8 1825,586.69 v2(1825,610)
CTL2: R14.1 U2.7 | length 750
  Signal Layer 1 w8: v2(1241.72,662.97) 1633.03,662.97 1707.87,588.13 1808.87,588.13 1827,570 v2(1860,570)
  Bottom Layer w8: R14.1@1206.4,677.97 1241.72,677.97 v2(1241.72,662.97) ; U2.7@1829.8,554.21 1829.8,564.8 1835,570 v2(1860,570)
CTL3: R15.1 U2.8 | length 734.8
  Signal Layer 1 w8: v2(1241.72,622.97) 1636.03,622.97 1686.75,572.25 1801.75,572.25 1839,535 v2(1860,535)
  Bottom Layer w8: R15.1@1206.4,637.97 1241.72,637.97 v2(1241.72,622.97) ; U2.8@1830.28,535 v2(1860,535)
DSCG: R18.1 U2.24 | length 211.9
  Top Layer w15: R18.1@1606.85,405 1606.85,536.85 1625,555 v2(1645,555)
  Bottom Layer w10: v2@1645.79,554.21 U2.24@1680.2,554.21
DVDD: C18.2 U2.5 U2.13 | length 373.3
  Top Layer w8: v2(1790,390) 1803.39,390 1829.8,416.42 1829.8,554.21 1790,594.02 v2(1790,610)
  Bottom Layer w8: U2.5@1784.53,579.8 1784.53,592.49 1790,597.96 v2(1790,610) ; v2@1790.31,389.69 C18.2@1820,389.69 1820,420 1809.8,430.2 U2.13@1804.21,430.2
FB: C15.2 C16.1 R12.1 R16.2 R21.1@1167.03,592.97 U1.8 | length 247
  Bottom Layer w8: U1.8@933.74,559.65 954.72,559.65 975.24,580.16 1049.84,580.16 1050,580.16 R12.1@1090,580.32 1100.32,580.32 1112.97,592.97 R21.1@1167.03,592.97
GDNG: R20.1 R21.2@1555,459.69 U2.22 | length 243.3
  Bottom Layer w8: R20.1@1515,459.37 R21.2@1555,459.37 ; R20.1@1515.31,465 1515.31,495.31 1534.84,514.84 U2.22@1680.2,514.84
GDNS: U2.23
GND: C1.2 C2.2 C3.2 C4.2 C6.2 C7.2 C8.2 C9.2 C10.2 C13.1 C14.2 C16.2 C17.2 C18.1 C19.2 C20.2 C21.2 C22.2 C23.2 C24.2 C25.2 Cin1.2 Cin2.2 Cin3.2 Cin4.2 Co1.2 Co2.2 Co3.2 Co4.2 Co5.2 D5.2 J1.1 J1.2 J1.3 J1.A1 J1.A12 J1.B1 J1.B12 J1.H1 J1.H2 J1.H3 J1.H4 J1.H5 J1.H6 NT2.1 R6.2 R10.1 R16.1 R19.2 RS1.1 U1.2 U1.7 U1.10 U1.11 U1.19 U1.29 U2.4 U2.17 U2.18 U2.25@1755,505 | length 1056.3
  Top Layer w10: 1075,30 1095,30 ; v3(1870,305) 1872.24,302.76 J1.2@1892.72,302.76
  Top Layer w15: v1(615,40) 625,40 640,25 688.65,25 688.65,24.13 773.47,24.13 774.35,25 815,25 v1(830,40)
  Signal Layer 2 w8: v2(870,64.11) 870,81 874,85 NT2.1@890,85
  Bottom Layer w8: U1.29@815.63,534.06 U1.2@815.63,559.65 ; U1.29@914.06,534.06 U1.7@914.06,559.65 914.06,579.06 934.53,599.53 C10.2@934.53,619.84 1009.53,619.84 1009.68,619.69 C16.2@1050,619.69 ; U2.18@1705.79,430.2 U2.17@1725.47,430.2 ; U2.25@1764.84,514.84 U2.4@1764.84,579.8
  Bottom Layer w10: U1.29@855,475 U1.19@855,410.04 855,360 869.69,345.31 C4.2@869.69,330 ; v2(870,290) C4.2@870,329.69 ; U1.29@874.68,494.68 U1.11@959.33,494.68 C6.2@1014.37,494.68 ; U1.29@894.37,514.37 U1.10@959.33,514.37 ; 1065,30 1095,30
  other v1: 135,40 230,40 355,40 480,40 915,40 1165,40 1255,40 1380,40 1505,40 1861,45 1650,85 1865,150 375,415 1475,465 275,475 100,550 200,550 275,595 1475,595 1950,600 2050,600 2150,600 100,650 200,650 1950,700 2050,700 2150,700
  other v2: 864.84,445.47 1755,459.72 814.84,484.84 864.84,484.84 919.84,484.84 1709.72,505 1755,505 1800.28,505 864.84,524.21 1755,550.28
HDRV1_N: C5.2 L3.1 Q2.1 Q2.2 Q2.3 Q4.5 Q4.6 Q4.7 Q4.8 Q4.9 U1.25 | length 307.4
  Top Layer w8: Q2.3@578.82,315 v2(605,315)
  Signal Layer 1 w8: v2(740,420) v2@740,470
  Bottom Layer w8: v2(605,315) 628.94,315 660,346.06 660,385 690.69,415.69 711,415.69 C5.2@715,419.69 ; C5.2@715.31,420 v2(740,420) ; v2(740,475) U1.25@770.35,475
  other v1: 665,145 700,145 735,145 665,190 700,190 735,190
HDRV1_P: Rg.1 U1.24 | length 151.7
  Bottom Layer w8: Rg.1@635.32,415 664.54,415 695.54,446 744.94,446 754.26,455.31 U1.24@770.35,455.31
HDRV2_N: C11.1 D4.2 L3.2 Q1.1 Q1.2 Q1.3 Q3.5 Q3.6 Q3.7 Q3.8 Q3.9 U1.15 | length 393.5
  Top Layer w8: v2(1080,310) 1083.94,310 1101.74,292.2 Q1.3@1148.98,292.2
  Bottom Layer w8: U1.15@933.74,410.04 944.65,410.04 980,374.68 980,350 ; D4.2@988.31,275 980,275 954.68,300.32 C11.1@954.68,345 1050,345 1080,315 v2(1080,310)
  other v1: 1005,145 1040,145 1075,145 1005,190 1040,190 1075,190
HDRV2_P: Q1.4 U1.16 | length 309.8
  Top Layer w8: v2(1080,280) 1093.39,266.61 Q1.4@1149.47,266.61
  Signal Layer 2 w8: v2(940,375) 940,370 1030,280 v2(1080,280)
  Bottom Layer w8: U1.16@914.06,410.04 914.06,398.08 937.13,375 v2(940,375) ; v2@1075,280 v2(1080,280)
ISNS: Q5.1 Q5.2 Q5.3 R17.1 U2.19 | length 205.4
  Top Layer w8: R17.1@1606.85,315 v2(1640.32,315)
  Signal Layer 2 w8: v2(1640.32,315) 1640.32,415.32 1650,425 v2(1650,443.39)
  Bottom Layer w8: v2(1650,443.39) 1675,443.39 1680.2,448.58 U2.19@1680.2,455.79
LDRV1: Q4.4 U1.22 | length 358.2
  Signal Layer 1 w10: v2(740,75) 770,105 v2(770,375)
  Bottom Layer w8: v2(770,375) 770,384.09 U1.22@795.94,410.04
LDRV2: Q3.4 U1.18 | length 517.8
  Top Layer w10: v2(1080,60) Q3.4@1080,87.36
  Signal Layer 1 w10: v2(885,365) 930,320 930,115.43 985.43,60 v2(1080,60)
  Bottom Layer w10: U1.18@874.69,410.04 874.69,375.31 v2(885,365)
MODE: R6.1 U1.1 | length 135
  Bottom Layer w8: R6.1@734.68,660 734.68,605 780.04,559.65 U1.1@795.94,559.65
NetC9_1: C9.1 R5.1 | length 35
  Bottom Layer w8: R5.1@934.53,659.84 C9.1@969.53,659.84
NetC12_1: C12.1 R7.1 U1.13 | length 100.6
  Bottom Layer w8: U1.13@959.33,455.31 974.37,455.31 1009.37,420.32 C12.1@1010,420.32 1045,420.32 R7.1@1045.32,420
NetC12_2: C12.2 R9.1 U1.12 | length 92
  Bottom Layer w8: U1.12@959.33,475 994.69,475 C12.2@1010,459.69 R9.1@1045,459.69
